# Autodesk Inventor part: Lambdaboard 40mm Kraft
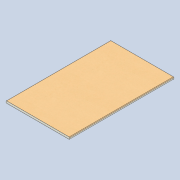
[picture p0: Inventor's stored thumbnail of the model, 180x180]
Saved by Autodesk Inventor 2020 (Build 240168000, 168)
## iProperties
Created: 2020-11
Part Number: Lambdaboard 40mm Kraft
Material: Generic
Document SubType Name: Modeling
Designer: Yolande
Density: 1 g/cm^3
Appearance: Default
Author: Yolande
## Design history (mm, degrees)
sketch "Sketch1"
  geometry: L1 (10, 0)-(1210, 0); L2 (1220, 10)-(1220, 30); L3 (1210, 40)-(10, 40); L4 (0, 30)-(0, 10); A1 r 10 centre (10, 30) between (10, 40) and (0, 30); A2 r 10 centre (10, 10) between (0, 10) and (10, 0); A3 r 10 centre (1210, 30) between (1220, 30) and (1210, 40); A4 r 10 centre (1210, 10) between (1210, 0) and (1220, 10); 3 further points
  constraints: 8 end point, 8 point on circle, 8 tangent, 6 point on line, 4 centre point, 3 equal radius, 3 perpendicular, 1 horizontal
  dimensions: "d0" = 1220 distance of point (0, 0) point (1220, 0); "d1" = 40 distance of point (1220, 0) point (1220, 40); "d2" = 10 radius of A1
extrude "Extrusion1" new body sketch "Sketch1" distance "d3" = 2000; taper "d4" = 0 deg
body "Solid1"
